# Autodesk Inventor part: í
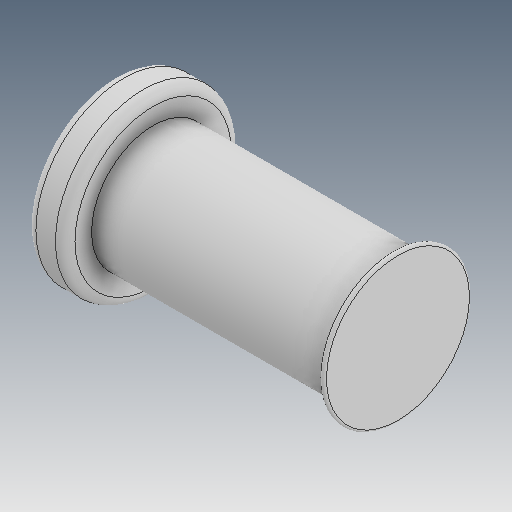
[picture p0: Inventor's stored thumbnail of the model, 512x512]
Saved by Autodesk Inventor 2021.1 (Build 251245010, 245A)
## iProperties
Created: 2020-03
Part Number: í
Material: Ogólny
Document SubType Name: Modeling
Designer: user
Density: 1 g/cm^3
Appearance: Domyślna
Author: user
Revision Number: ÈÎºÎ
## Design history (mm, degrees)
feature "Ô²½Ç1"
node "Bryła1"
